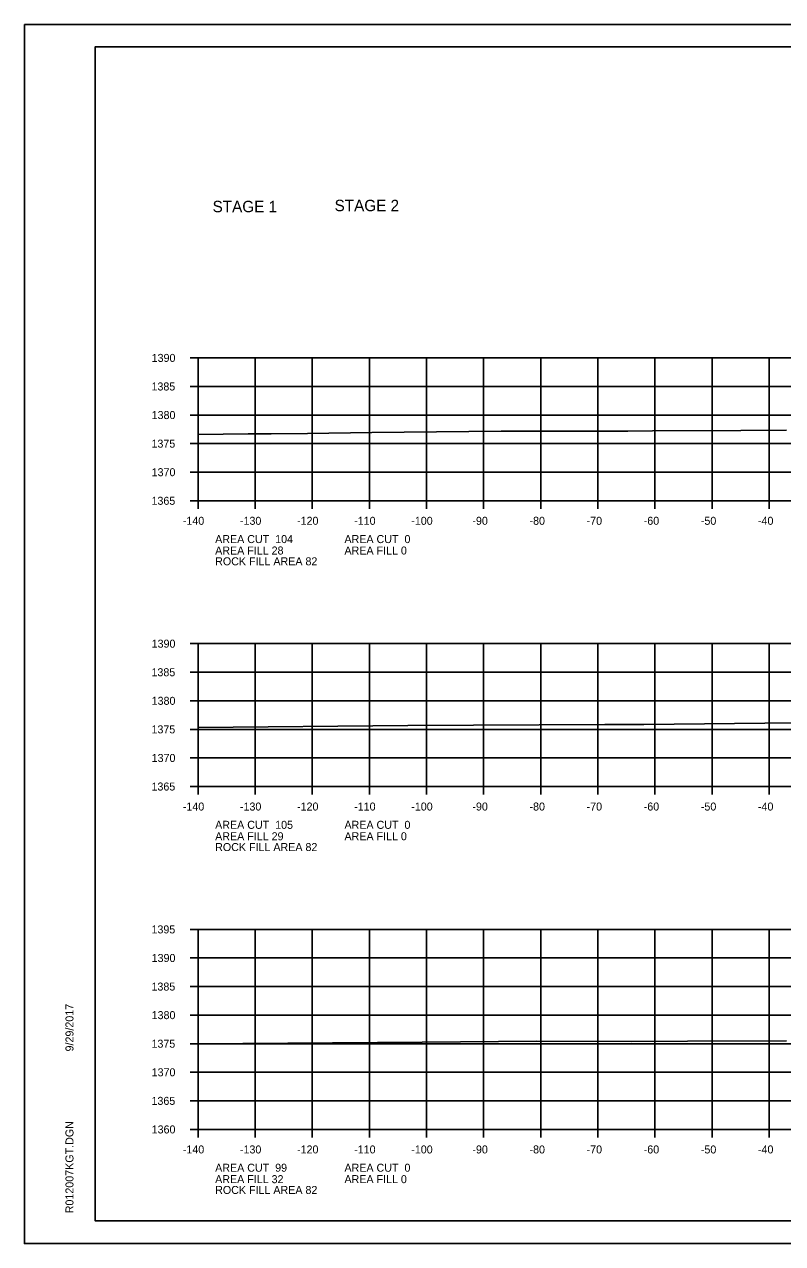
# Model space of a CAD drawing. Extents: x 1374311 to 1383814, y 384102 to 406278.
# Drawn here: x 1382550.5 to 1382683.2, y 385972.6 to 386185.9 of the extents above; entities that cross this region are included whole.
import ezdxf

# ---------------------------------------------------------------- set-up
doc = ezdxf.new("R2010")
doc.units = 0
for name, color, linetype in [('R_Axis', 7, 'Continuous'), ('R_Axis Annot', 7, 'Continuous'), ('R_Border', 7, 'Continuous'), ('R_Exist Surface', 7, 'Continuous'), ('R_Grid', 7, 'Continuous'), ('R_No Plot', 7, 'Continuous'), ('R_Water', 7, 'Continuous')]:
    doc.layers.add(name, color=color, linetype=linetype)

msp = doc.modelspace()

# ---------------------------------------------------------------- linework, layer by layer
at = {"layer": 'R_Axis'}
for p, q in [((1382579.46, 386127.56), (1382580.86, 386127.56)), ((1382580.86, 386102.56), (1382580.86, 386127.56)), ((1382579.46, 386122.56), (1382580.86, 386122.56)), ((1382579.46, 386117.56), (1382580.86, 386117.56)), ((1382579.46, 386112.56), (1382580.86, 386112.56)), ((1382579.46, 386107.56), (1382580.86, 386107.56)), ((1382579.46, 386102.56), (1382580.86, 386102.56)), ((1382580.86, 386102.56), (1382860.86, 386102.56)), ((1382580.86, 386101.16), (1382580.86, 386102.56)), ((1382590.86, 386101.16), (1382590.86, 386102.56)), ((1382600.86, 386101.16), (1382600.86, 386102.56)), ((1382610.86, 386101.16), (1382610.86, 386102.56)), ((1382620.86, 386101.16), (1382620.86, 386102.56)), ((1382630.86, 386101.16), (1382630.86, 386102.56)), ((1382640.86, 386101.16), (1382640.86, 386102.56)), ((1382650.86, 386101.16), (1382650.86, 386102.56)), ((1382660.86, 386101.16), (1382660.86, 386102.56)), ((1382670.86, 386101.16), (1382670.86, 386102.56)), ((1382680.86, 386101.16), (1382680.86, 386102.56)), ((1382579.46, 386077.56), (1382580.86, 386077.56)), ((1382580.86, 386052.56), (1382580.86, 386077.56)), ((1382579.46, 386072.56), (1382580.86, 386072.56)), ((1382579.46, 386067.56), (1382580.86, 386067.56)), ((1382579.46, 386062.56), (1382580.86, 386062.56)), ((1382579.46, 386057.56), (1382580.86, 386057.56)), ((1382579.46, 386052.56), (1382580.86, 386052.56)), ((1382580.86, 386052.56), (1382860.86, 386052.56)), ((1382580.86, 386051.16), (1382580.86, 386052.56)), ((1382590.86, 386051.16), (1382590.86, 386052.56)), ((1382600.86, 386051.16), (1382600.86, 386052.56)), ((1382610.86, 386051.16), (1382610.86, 386052.56)), ((1382620.86, 386051.16), (1382620.86, 386052.56)), ((1382630.86, 386051.16), (1382630.86, 386052.56)), ((1382640.86, 386051.16), (1382640.86, 386052.56)), ((1382650.86, 386051.16), (1382650.86, 386052.56)), ((1382660.86, 386051.16), (1382660.86, 386052.56)), ((1382670.86, 386051.16), (1382670.86, 386052.56)), ((1382680.86, 386051.16), (1382680.86, 386052.56)), ((1382579.46, 386027.56), (1382580.86, 386027.56)), ((1382580.86, 385992.56), (1382580.86, 386027.56)), ((1382579.46, 386022.56), (1382580.86, 386022.56)), ((1382579.46, 386017.56), (1382580.86, 386017.56)), ((1382579.46, 386012.56), (1382580.86, 386012.56)), ((1382579.46, 386007.56), (1382580.86, 386007.56)), ((1382579.46, 386002.56), (1382580.86, 386002.56)), ((1382579.46, 385997.56), (1382580.86, 385997.56)), ((1382579.46, 385992.56), (1382580.86, 385992.56)), ((1382580.86, 385992.56), (1382860.86, 385992.56)), ((1382580.86, 385991.16), (1382580.86, 385992.56)), ((1382590.86, 385991.16), (1382590.86, 385992.56)), ((1382600.86, 385991.16), (1382600.86, 385992.56)), ((1382610.86, 385991.16), (1382610.86, 385992.56)), ((1382620.86, 385991.16), (1382620.86, 385992.56)), ((1382630.86, 385991.16), (1382630.86, 385992.56)), ((1382640.86, 385991.16), (1382640.86, 385992.56)), ((1382650.86, 385991.16), (1382650.86, 385992.56)), ((1382660.86, 385991.16), (1382660.86, 385992.56)), ((1382670.86, 385991.16), (1382670.86, 385992.56)), ((1382680.86, 385991.16), (1382680.86, 385992.56))]:
    msp.add_line(p, q, dxfattribs=at)
at = {"layer": 'R_Border'}
for p, q in [((1382562.86, 386182.02), (1382879.04, 386182.02)), ((1382562.86, 385976.56), (1382562.86, 386182.02)), ((1382562.86, 385976.56), (1382562.86, 385976.56)), ((1382879.04, 385976.56), (1382562.86, 385976.56))]:
    msp.add_line(p, q, dxfattribs=at)
at = {"layer": 'R_Exist Surface'}
for points in [[(1382580.86, 386114.14), (1382589.63, 386114.25), (1382593.68, 386114.29), (1382600.01, 386114.36), (1382611.29, 386114.48), (1382633.95, 386114.72), (1382635.34, 386114.72), (1382635.6, 386114.72), (1382656.13, 386114.76), (1382660.42, 386114.79), (1382675.88, 386114.84), (1382683.87, 386114.89)], [(1382580.86, 386062.9), (1382617.58, 386063.24), (1382652.08, 386063.41), (1382656.5, 386063.42), (1382658.9, 386063.44), (1382706.63, 386063.93), (1382707.46, 386064), (1382713.6, 386064.14), (1382724.25, 386064.28), (1382741.52, 386064.45), (1382753.11, 386064.56), (1382762.33, 386064.69), (1382774.72, 386064.76), (1382785.01, 386064.77), (1382816.56, 386065.08), (1382824.33, 386065.18), (1382834.04, 386065.11), (1382835.86, 386065.1), (1382848.09, 386065.36), (1382860.86, 386066.23)], [(1382580.86, 386007.51), (1382620.12, 386007.83), (1382640.19, 386007.99), (1382656.79, 386007.97), (1382666.57, 386008.03), (1382683.91, 386008.06)]]:
    msp.add_lwpolyline(points, dxfattribs=at)
at = {"layer": 'R_Grid'}
for p, q in [((1382580.86, 386127.56), (1382860.86, 386127.56)), ((1382580.86, 386102.56), (1382580.86, 386127.56)), ((1382590.86, 386102.56), (1382590.86, 386127.56)), ((1382600.86, 386102.56), (1382600.86, 386127.56)), ((1382610.86, 386102.56), (1382610.86, 386127.56)), ((1382620.86, 386102.56), (1382620.86, 386127.56)), ((1382630.86, 386102.56), (1382630.86, 386127.56)), ((1382640.86, 386102.56), (1382640.86, 386127.56)), ((1382650.86, 386102.56), (1382650.86, 386127.56)), ((1382660.86, 386102.56), (1382660.86, 386127.56)), ((1382670.86, 386102.56), (1382670.86, 386127.56)), ((1382680.86, 386102.56), (1382680.86, 386127.56)), ((1382580.86, 386122.56), (1382860.86, 386122.56)), ((1382580.86, 386117.56), (1382860.86, 386117.56)), ((1382580.86, 386112.56), (1382860.86, 386112.56)), ((1382580.86, 386107.56), (1382860.86, 386107.56)), ((1382580.86, 386102.56), (1382860.86, 386102.56)), ((1382580.86, 386077.56), (1382860.86, 386077.56)), ((1382580.86, 386052.56), (1382580.86, 386077.56)), ((1382590.86, 386052.56), (1382590.86, 386077.56)), ((1382600.86, 386052.56), (1382600.86, 386077.56)), ((1382610.86, 386052.56), (1382610.86, 386077.56)), ((1382620.86, 386052.56), (1382620.86, 386077.56)), ((1382630.86, 386052.56), (1382630.86, 386077.56)), ((1382640.86, 386052.56), (1382640.86, 386077.56)), ((1382650.86, 386052.56), (1382650.86, 386077.56)), ((1382660.86, 386052.56), (1382660.86, 386077.56)), ((1382670.86, 386052.56), (1382670.86, 386077.56)), ((1382680.86, 386052.56), (1382680.86, 386077.56)), ((1382580.86, 386072.56), (1382860.86, 386072.56)), ((1382580.86, 386067.56), (1382860.86, 386067.56)), ((1382580.86, 386062.56), (1382860.86, 386062.56)), ((1382580.86, 386057.56), (1382860.86, 386057.56)), ((1382580.86, 386052.56), (1382860.86, 386052.56)), ((1382580.86, 386027.56), (1382860.86, 386027.56)), ((1382580.86, 385992.56), (1382580.86, 386027.56)), ((1382590.86, 385992.56), (1382590.86, 386027.56)), ((1382600.86, 385992.56), (1382600.86, 386027.56)), ((1382610.86, 385992.56), (1382610.86, 386027.56)), ((1382620.86, 385992.56), (1382620.86, 386027.56)), ((1382630.86, 385992.56), (1382630.86, 386027.56)), ((1382640.86, 385992.56), (1382640.86, 386027.56)), ((1382650.86, 385992.56), (1382650.86, 386027.56)), ((1382660.86, 385992.56), (1382660.86, 386027.56)), ((1382670.86, 385992.56), (1382670.86, 386027.56)), ((1382680.86, 385992.56), (1382680.86, 386027.56)), ((1382580.86, 386022.56), (1382860.86, 386022.56)), ((1382580.86, 386017.56), (1382860.86, 386017.56)), ((1382580.86, 386012.56), (1382860.86, 386012.56)), ((1382580.86, 386007.56), (1382860.86, 386007.56)), ((1382580.86, 386002.56), (1382860.86, 386002.56)), ((1382580.86, 385997.56), (1382860.86, 385997.56)), ((1382580.86, 385992.56), (1382860.86, 385992.56))]:
    msp.add_line(p, q, dxfattribs=at)
at = {"layer": 'R_No Plot'}
for p, q in [((1382550.46, 386185.92), (1382883.79, 386185.92)), ((1382550.46, 385972.59), (1382883.79, 385972.59))]:
    msp.add_line(p, q, dxfattribs=at)
for points in [[(1382550.45, 386185.92), (1382883.79, 386185.92), (1382883.79, 385972.58), (1382550.45, 385972.58)], [(1382796.78, 386182.02), (1382796.78, 386172.14), (1382832.51, 386172.14), (1382832.51, 386169.22), (1382855.71, 386169.22), (1382855.71, 386146.01), (1382879.04, 386146.01), (1382879.04, 385976.56), (1382562.86, 385976.56), (1382562.86, 386182.02)]]:
    msp.add_lwpolyline(points, close=True, dxfattribs=at)

# ---------------------------------------------------------------- texts
at = {"layer": 'R_Axis Annot'}
for s, p in [('1390', (1382572.74, 386126.86)), ('1385', (1382572.71, 386121.86)), ('1380', (1382572.74, 386116.86)), ('1375', (1382572.71, 386111.86)), ('1370', (1382572.74, 386106.86)), ('1365', (1382572.71, 386101.86)), ('-140', (1382578.2, 386098.36)), ('-130', (1382588.2, 386098.36)), ('-120', (1382598.2, 386098.36)), ('-110', (1382608.2, 386098.36)), ('-100', (1382618.2, 386098.36)), ('-90', (1382628.9, 386098.36)), ('-80', (1382638.9, 386098.36)), ('-70', (1382648.9, 386098.36)), ('-60', (1382658.9, 386098.36)), ('-50', (1382668.9, 386098.36)), ('-40', (1382678.9, 386098.36)), ('AREA CUT  104', (1382583.86, 386095.16)), ('AREA CUT  0', (1382606.5, 386095.16)), ('AREA FILL 28', (1382583.86, 386093.16)), ('AREA FILL 0', (1382606.5, 386093.16)), ('ROCK FILL AREA 82', (1382583.86, 386091.27)), ('1390', (1382572.74, 386076.86)), ('1385', (1382572.71, 386071.86)), ('1380', (1382572.74, 386066.86)), ('1375', (1382572.71, 386061.86)), ('1370', (1382572.74, 386056.86)), ('1365', (1382572.71, 386051.86)), ('-140', (1382578.2, 386048.36)), ('-130', (1382588.2, 386048.36)), ('-120', (1382598.2, 386048.36)), ('-110', (1382608.2, 386048.36)), ('-100', (1382618.2, 386048.36)), ('-90', (1382628.9, 386048.36)), ('-80', (1382638.9, 386048.36)), ('-70', (1382648.9, 386048.36)), ('-60', (1382658.9, 386048.36)), ('-50', (1382668.9, 386048.36)), ('-40', (1382678.9, 386048.36)), ('AREA CUT  105', (1382583.86, 386045.16)), ('AREA CUT  0', (1382606.5, 386045.16)), ('AREA FILL 29', (1382583.86, 386043.16)), ('AREA FILL 0', (1382606.5, 386043.16)), ('ROCK FILL AREA 82', (1382583.86, 386041.27)), ('1395', (1382572.71, 386026.86)), ('1390', (1382572.74, 386021.86)), ('1385', (1382572.71, 386016.86)), ('1380', (1382572.74, 386011.86)), ('1375', (1382572.71, 386006.86)), ('1370', (1382572.74, 386001.86)), ('1365', (1382572.71, 385996.86)), ('1360', (1382572.74, 385991.86)), ('-140', (1382578.2, 385988.36)), ('-130', (1382588.2, 385988.36)), ('-120', (1382598.2, 385988.36)), ('-110', (1382608.2, 385988.36)), ('-100', (1382618.2, 385988.36)), ('-90', (1382628.9, 385988.36)), ('-80', (1382638.9, 385988.36)), ('-70', (1382648.9, 385988.36)), ('-60', (1382658.9, 385988.36)), ('-50', (1382668.9, 385988.36)), ('-40', (1382678.9, 385988.36)), ('AREA CUT  99', (1382583.86, 385985.16)), ('AREA CUT  0', (1382606.5, 385985.16)), ('AREA FILL 32', (1382583.86, 385983.16)), ('AREA FILL 0', (1382606.5, 385983.16)), ('ROCK FILL AREA 82', (1382583.86, 385981.27))]:
    msp.add_text(s, height=1.4, dxfattribs=at).set_placement(p)
at = {"layer": 'R_Border'}
for s, p in [('9/29/2017', (1382559.05, 386006.21)), ('R012007KGT.DGN', (1382559.05, 385977.89))]:
    msp.add_text(s, height=1.4, rotation=90, dxfattribs=at).set_placement(p)
at = {"layer": 'R_Water'}
for s, p in [('STAGE 1', (1382583.41, 386153.05)), ('STAGE 2', (1382604.77, 386153.23))]:
    msp.add_text(s, height=2, dxfattribs=at).set_placement(p)

doc.saveas('drawing.dxf')
